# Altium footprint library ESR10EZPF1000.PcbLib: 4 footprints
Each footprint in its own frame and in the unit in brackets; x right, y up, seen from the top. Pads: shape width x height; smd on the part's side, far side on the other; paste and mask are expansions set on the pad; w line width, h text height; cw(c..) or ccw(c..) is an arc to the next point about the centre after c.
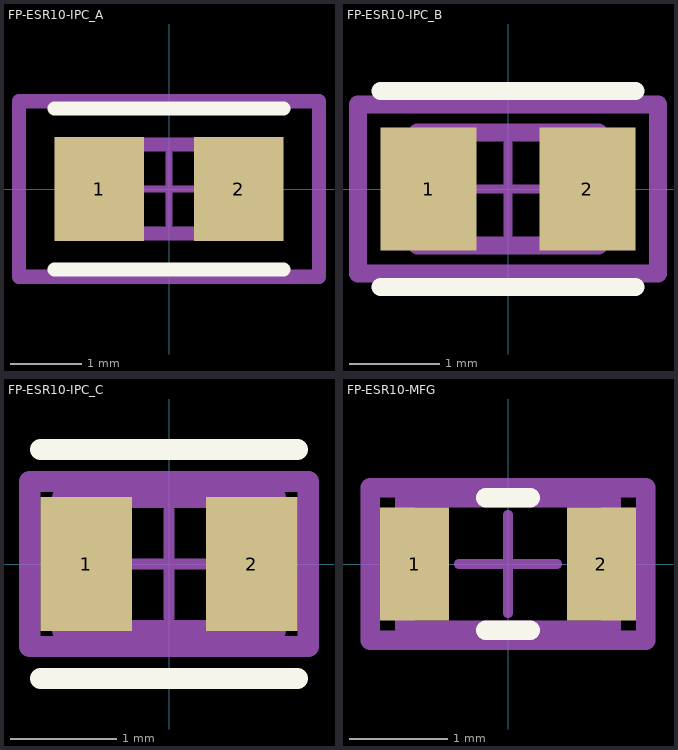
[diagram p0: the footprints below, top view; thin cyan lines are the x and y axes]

## FP-ESR10-IPC_A [mm]
pads (2):
  rect 1.258x1.462 smd paste+0 mask+0: 1(-0.977,0) 2(0.977,0)
Top Overlay:
  lines w0.2: -1.606,-1.131 1.606,-1.131 ; -1.606,1.131 1.606,1.131
Mechanical 5:
  lines w0.2: -2.106,-1.231 2.106,-1.231 2.106,1.231 -2.106,1.231 -2.106,-1.231
  text ".Designator" at 0,0.188 h1
Mechanical 13:
  lines w0.2: -1,-0.625 1,-0.625 1,0.625 -1,0.625 -1,-0.625
Mechanical 15:
  lines w0.2: -2.106,-1.231 2.106,-1.231 2.106,1.231 -2.106,1.231 -2.106,-1.231
Mechanical 16:
  lines w0.1: -0.5,0 0.5,0 ; 0,-0.5 0,0.5
3D body "Res_Rohm_ESR10EZPF49R9_eec.STEP": height 0.25, standoff 0, extent -2.106,-1.231 2.106,1.231

## FP-ESR10-IPC_B [mm]
pads (2):
  rect 1.058x1.362 smd paste+0 mask+0: 1(-0.877,0) 2(0.877,0)
Top Overlay:
  lines w0.2: -1.406,-1.081 1.406,-1.081 ; -1.406,1.081 1.406,1.081
Mechanical 5:
  lines w0.2: -1.656,-0.931 1.656,-0.931 1.656,0.931 -1.656,0.931 -1.656,-0.931
  text ".Designator" at 0,0.188 h1
Mechanical 13:
  lines w0.2: -1,-0.625 1,-0.625 1,0.625 -1,0.625 -1,-0.625
Mechanical 15:
  lines w0.2: -1.656,-0.931 1.656,-0.931 1.656,0.931 -1.656,0.931 -1.656,-0.931
Mechanical 16:
  lines w0.1: -0.5,0 0.5,0 ; 0,-0.5 0,0.5
3D body "Res_Rohm_ESR10EZPF49R9_eec.STEP": height 0.25, standoff 0, extent -1.656,-0.931 1.656,0.931

## FP-ESR10-IPC_C [mm]
pads (2):
  rect 0.858x1.262 smd paste+0 mask+0: 1(-0.777,0) 2(0.777,0)
Top Overlay:
  lines w0.2: -1.206,-1.075 1.206,-1.075 ; -1.206,1.075 1.206,1.075
Mechanical 5:
  lines w0.2: -1.306,-0.775 1.306,-0.775 1.306,0.775 -1.306,0.775 -1.306,-0.775
  text ".Designator" at 0,0.188 h1
Mechanical 13:
  lines w0.2: -1,-0.625 1,-0.625 1,0.625 -1,0.625 -1,-0.625
Mechanical 15:
  lines w0.2: -1.306,-0.775 1.306,-0.775 1.306,0.775 -1.306,0.775 -1.306,-0.775
Mechanical 16:
  lines w0.1: -0.5,0 0.5,0 ; 0,-0.5 0,0.5
3D body "Res_Rohm_ESR10EZPF49R9_eec.STEP": height 0.25, standoff 0, extent -1.306,-0.775 1.306,0.775

## FP-ESR10-MFG [mm]
pads (2):
  rect 0.7x1.15 smd paste+0 mask+0: 1(-0.95,0) 2(0.95,0)
Top Overlay:
  lines w0.2: -0.225,-0.675 0.225,-0.675 ; -0.225,0.675 0.225,0.675
Mechanical 5:
  lines w0.2: -1.4,-0.775 1.4,-0.775 1.4,0.775 -1.4,0.775 -1.4,-0.775
  text ".Designator" at 0,0.188 h1
Mechanical 13:
  lines w0.2: -1.05,-0.675 1.05,-0.675 1.05,0.675 -1.05,0.675 -1.05,-0.675
Mechanical 15:
  lines w0.2: -1.4,-0.775 1.4,-0.775 1.4,0.775 -1.4,0.775 -1.4,-0.775
Mechanical 16:
  lines w0.1: -0.5,0 0.5,0 ; 0,-0.5 0,0.5
3D body "Res_Rohm_ESR10EZPF49R9_eec.STEP": height 0.25, standoff 0, extent -1.4,-0.775 1.4,0.775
